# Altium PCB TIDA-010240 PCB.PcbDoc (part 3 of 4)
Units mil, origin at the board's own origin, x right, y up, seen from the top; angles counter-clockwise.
Board outline 5108.27 x 5374.02 mil, 4 copper layers (Top Layer, GND, PWR, Bottom Layer), stack 73.068 mil thick; 370 components, 162 nets, 1073 pads, 556 vias.
Unrouted connection lines stored in the file: 6.
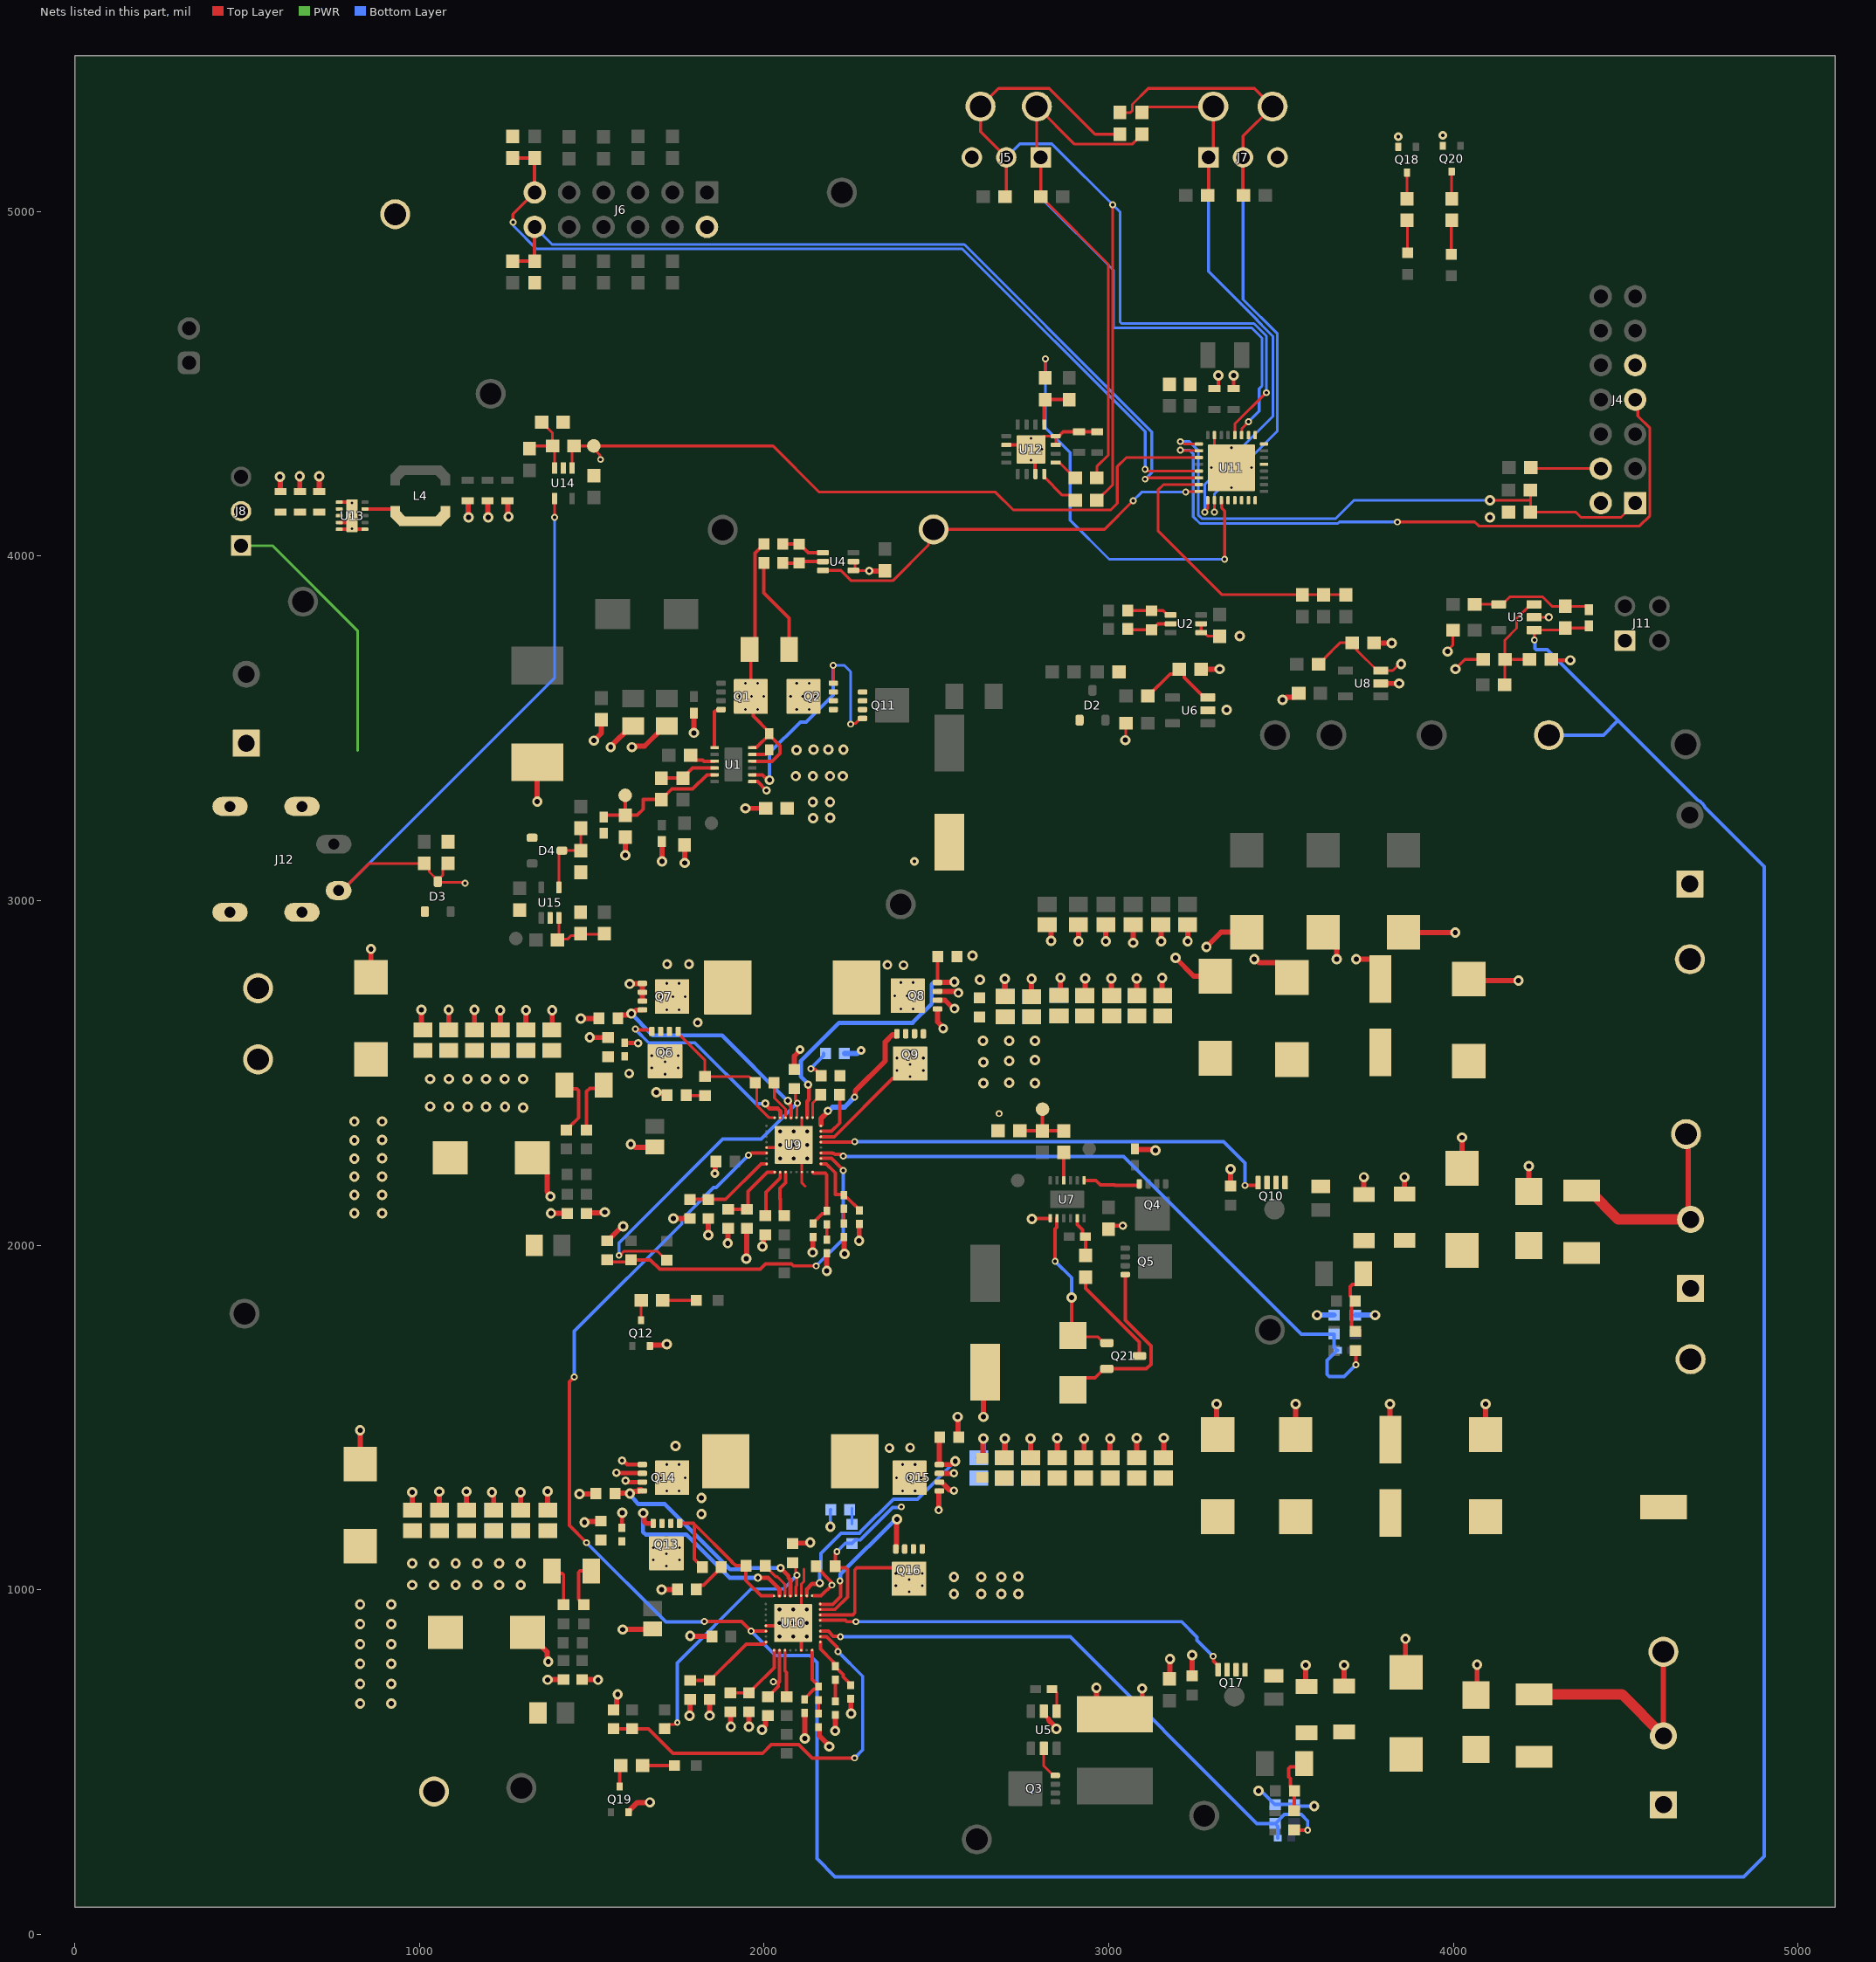
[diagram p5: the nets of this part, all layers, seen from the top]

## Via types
v1: diameter 30, hole 15, Top Layer to Bottom Layer, tented both sides, 281 vias
v2: diameter 19.68, hole 7.87, Top Layer to Bottom Layer, 102 vias
v3: diameter 20, hole 10, Top Layer to Bottom Layer, tented both sides, 99 vias
v4: diameter 24, hole 12, Top Layer to Bottom Layer, tented both sides, 19 vias
v5: diameter 23.62, hole 11.81, Top Layer to Bottom Layer, 18 vias
v6: diameter 19.68, hole 7.87, Top Layer to Bottom Layer, tented both sides, 14 vias
v7: diameter 28, hole 14, Top Layer to Bottom Layer, tented both sides, 13 vias
v8: diameter 25, hole 10, Top Layer to Bottom Layer, tented both sides, 8 vias
v9: diameter 18, hole 8, Top Layer to Bottom Layer, tented both sides, 2 vias

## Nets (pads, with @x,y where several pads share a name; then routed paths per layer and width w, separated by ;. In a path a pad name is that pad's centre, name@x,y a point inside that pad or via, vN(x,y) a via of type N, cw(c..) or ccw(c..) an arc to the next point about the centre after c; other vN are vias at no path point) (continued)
GND: C1.2 C2.2 C3.2 C4.2 C5.2 C6.2 C7.2 C8.2 C9.2 C10.2 C11.2 C12.2 C13.2 C16.2 C17.2 C18.2 C19.2 C21.2 C22.2 C25.2 C26.2 C27.2 C28.2 C29.2 C30.2 C32.2 C33.2 C34.2 C35.2 C36.2 C37.2 C38.2 C39.2 C40.2 C41.2 C42.2 C43.2 C45.2 C46.2 C47.2 C48.2 C49.2 C50.2 C51.2 C52.2 C53.2 C54.2 C57.2 C58.2 C59.2 C62.2 C63.1 C66.2 C67.2 C68.2 C69.2 C70.2 C71.2 C72.2 C73.2 C74.2 C75.1 C76.2 C77.1 C78.2 C79.2 C80.2 C81.2 C82.2 C83.2 C84.2 C85.1 C86.2 C87.2 C88.2 C89.2 C90.2 C91.2 C92.2 C93.2 C94.2 C95.2 C96.2 C97.2 C99.2 C100.2 C101.2 C102.2 C103.2 C104.2 C105.2 C106.2 C107.2 C108.2 C111.2 C112.2 C113.2 C116.2 C117.1 C120.2 C121.2 C122.2 C123.2 C124.2 C125.2 C126.2 C127.2 C128.2 C129.1 C130.2 C131.1 C132.2 C133.2 C134.2 C135.2 C136.2 C137.2 C138.2 C139.2 C140.2 C141.2 C142.2 C143.2 C144.2 C145.2 C146.2 C147.2 C148.2 C149.2 C150.2 C151.2 C152.2 C153.2 C154.2 C155.2 C156.2 C157.2 D1.1 D2.1 D3.1 D4.1 D5.2 D7.2 GND.1 J1.1 J2.1 J3.1 J4.9 J5.3 J6.2 J7.3 J10.1 J11.1 J12.2 Q7.1 Q7.2 Q7.3 Q8.1 Q8.2 Q8.3 Q12.2 Q14.1 Q14.2 Q14.3 Q15.1 Q15.2 Q15.3 Q18.2 Q19.2 Q20.2 R8.1 R9.1 R17.1 R21.1 R27.1 R31.1 R40.1 R42.1 R43.1 R44.2 R51.1 R55.1 R64.1 R66.1 R67.1 R68.2 R85.1 R88.1 R89.1 R91.1 R92.1 R99.1 R100.1 TP12.1 TP13.1 TP14.1 TP15.1 TP17.1 U1.7 U2.1 U2.2 U3.2 U4.1 U4.2 U5.2 U6.2 U7.7 U8.2 U9.5 U9.14 U9.27 U9.33 U10.5 U10.14 U10.27 U10.33 U11.31 U11.33 U12.6 U12.11 U12.15 U12.16 U12.17@2774.5,4310.15 U13.1 U13.4 U13.5 U13.6 U13.11@804.52,4117.36 U14.2 U15.2 | length 11320.9
  Top Layer w8: U9.5@2007.15,2283.52 2038.64,2283.52 v5(2046.52,2291.39) ; v5(2085.89,2291.39) 2109.51,2267.77 U9.14@2109.51,2212.65 2109.51,2181.08 2119.01,2171.58 ; U9.27@2109.51,2370.54 2109.51,2342.51 2121.26,2330.76 v5(2125.26,2330.76) ; 2115.25,1059.71 2115.25,1023.53 2107.71,1016 U10.27@2107.71,982.81 2107.71,954.78 2119.46,943.03 v5(2123.46,943.03) ; U4.1@2259.11,3958.74 2259.82,3958.03 2263.37,3961.58 2263.37,3980.45 2259.49,3984.33 U4.2@2259.11,3984.33 ; U4.1@2259.84,3958.01 2304.28,3958.01 v4(2305,3957.28) ; v2(2774.5,4341.65) 2806,4341.65 2812.89,4348.54 U12.16@2846.35,4348.54 U12.15@2846.35,4322.95 ; v1(3048.55,3465.98) 3049.41,3466.84 3049.41,3514.24 C25.2@3050.28,3515.1 ; U2.2@3267.99,3803.81 U2.1@3267.99,3778.22 3276.85,3778.22 3287.17,3767.9 C13.2@3321.93,3767.9 ; U11.31@3306.82,4351.31 3306.82,4320.74 3312.66,4314.9 v2(3356.03,4314.9) ; v1(3983.57,3723.21) 3983.57,3727.27 3998.85,3742.54 C19.2@3998.85,3785.38 ; v1(4005.88,3672.43) 4033.49,3700.04 R9.1@4086.5,3700.04 ; U3.2@4234.08,3822.78 v4(4277.02,3822.78)
  Top Layer w10: U13.5@767.12,4077.99 802.55,4077.99 v2(804.52,4079.96) 806.49,4077.99 U13.6@841.92,4077.99 ; U13.4@767.12,4097.68 791.34,4097.68 804.52,4110.85 v2(804.52,4117.36) ; U13.1@767.12,4156.73 767.17,4156.68 802.6,4156.68 v2(804.52,4154.77) ; U1.7@1965.61,3345.86 1980.78,3345.86 v4(2006.74,3319.9) ; U10.5@2005.35,895.79 2076.22,895.79 v5(2084.09,903.66) ; U10.14@2107.71,824.92 2107.71,852.54 2119.46,864.29 v5(2123.46,864.29) ; U12.6@2702.65,4322.95 2737.16,4322.95 2743,4317.1 v2(2743,4310.15) ; v2(2774.5,4278.65) 2780.9,4278.65 2785.74,4273.81 2785.74,4252.31 2786.39,4251.66 2786.39,4248.06 2787.3,4247.16 U12.11@2787.3,4238.3 ; v1(2777.18,2076.81) 2778.14,2077.77 2829.93,2077.77 2830.01,2077.85 U7.7@2830.01,2078.74 ; U12.16@2846.35,4348.54 2855.21,4348.54 2867.59,4360.92 C144.2@2966.27,4360.92 ; C146.2@3306.82,4486.06 3312.61,4486.06 3317.61,4491.06 v1(3317.61,4524.63) ; C147.2@3362.13,4486.06 v1(3362.13,4524.63)
  Top Layer w12: v4(1571.29,1339.99) 1572.18,1339.1 1645.8,1339.1 Q14.2@1646.69,1338.21 ; C108.2@1587.04,1179.94 1587.83,1180.73 1587.83,1222.97 v1(1588.63,1223.77) ; v4(1588.07,1375.03) 1591.32,1375.03 1602.56,1363.8 Q14.1@1646.69,1363.8 ; C54.2@1595.53,2587.53 1596.13,2586.94 1633.51,2586.94 v4(1634.1,2586.35) ; v4(1598.1,1316.55) 1601.35,1316.55 1605.28,1312.62 Q14.3@1646.69,1312.62 ; U5.2@2811.56,639.95 2826.15,625.36 2826.15,621.48 ; C28.2@2999.26,2047.24 3011.22,2059.2 3011.22,2057.48 3011.96,2056.74 v4(3040.81,2056.74) ; C18.2@4284.03,3700.04 4286.22,3697.85 v1(4339.14,3697.85)
  Top Layer w15: v1(595.36,4230.34) 596.18,4229.52 596.18,4188.24 C148.2@597,4187.42 ; v1(652.51,4231.69) 652.76,4231.44 652.76,4187.67 C149.2@653.01,4187.42 ; v1(708.81,4231.95) 709.06,4231.7 709.06,4187.67 C150.2@709.31,4187.42 ; C99.2@827.72,1364.92 v1(827.72,1462.99) ; C45.2@859.27,2777.75 v1(859.27,2860) ; C120.2@979.31,1231.06 v1(979.31,1282.89) ; v1(1005.41,2683.17) 1005.41,2629.12 C49.2@1009.89,2624.64 ; v1(1057.53,1285.12) 1057.53,1231.48 C121.2@1057.95,1231.06 ; C50.2@1084.69,2624.64 v1(1084.69,2683.17) ; C122.2@1136.59,1231.06 v1(1136.59,1285.12) ; C151.2@1140.15,4160.67 1141.09,4159.72 1141.09,4113.78 v1(1142.04,4112.83) ; C66.2@1159.5,2624.64 v1(1159.5,2683.17) ; C152.2@1197.63,4160.67 1198.58,4159.72 1198.58,4113.78 v1(1199.53,4112.83) ; v1(1210.25,1282.89) 1210.25,1278.83 1215.22,1273.86 C123.2@1215.22,1231.06 ; C67.2@1234.3,2624.64 v1(1234.3,2682.02) ; C153.2@1255.12,4160.67 1256.72,4159.07 1256.72,4116.33 v1(1258.32,4114.73) ; v1(1293.09,1282.89) 1293.09,1231.83 C103.2@1293.86,1231.06 ; C68.2@1309.1,2624.64 v1(1309.1,2682.02) ; C100.2@1313.55,876.4 1315.51,876.4 1356.24,835.67 1356.24,833.7 1370.72,819.23 1370.72,794.7 v1(1373.59,791.83) ; C46.2@1327.38,2254.25 1329.35,2254.25 1370.08,2213.52 1370.08,2155.75 1380,2145.83 v1(1380,2141.77) ; v1(1341.78,3288.16) D1.1@1341.78,3401.72 ; v1(1371.44,738.88) 1371.85,739.28 1417.67,739.28 C124.2@1418.07,739.68 ; v1(1371.44,1286.12) 1371.44,1232.11 C104.2@1372.5,1231.06 ; v1(1381.39,2092.56) C70.2@1428.41,2092.56 ; C69.2@1383.9,2624.64 1385.1,2625.84 v1(1385.1,2682.02) ; v1(1464.47,1278.17) 1464.96,1278.66 1511.39,1278.66 C116.2@1511.88,1279.15 ; v1(1468.18,2658.46) C62.2@1520.73,2658.46 ; C125.2@1471.98,739.68 1472.38,739.28 1517.74,739.28 v1(1518.14,738.88) ; v1(1478.87,1196.19) 1480.59,1197.91 1524.57,1197.91 C107.2@1526.29,1199.63 ; C71.2@1484.38,2092.56 1486.2,2094.37 1535.88,2094.37 v1(1537.69,2096.19) ; v1(1494.08,2603.28) 1494.46,2602.91 1546.82,2602.91 C53.2@1547.2,2602.53 ; v1(1506,3464.73) 1527.61,3486.34 C9.2@1527.61,3525.13 ; R40.1@1544.8,2013.01 1545.78,2013.01 1587.77,2055 v1(1591,2055) ; v1(1554.88,3445.68) 1554.88,3447.86 1555.08,3447.86 1613.99,3506.78 C10.2@1620.49,3506.78 ; R64.1@1562.79,652.09 1563.78,652.09 1572.03,660.34 1572.03,689.71 1575.04,692.72 v1(1575.04,696.78) ; v1(1589.37,884.72) 1590.3,885.65 1675.58,885.65 C128.2@1676.51,886.58 ; v1(1597,3132.14) R8.1@1597,3185.03 ; Q19.2@1606.54,354.6 1608.29,356.35 1608.29,358.91 1631.24,381.85 1667.49,381.85 v1(1668.74,383.1) ; v1(1610,2758.6) 1610.67,2759.27 1646.15,2759.27 Q7.1@1646.82,2759.94 Q7.2@1646.82,2734.35 Q7.3@1646.82,2708.76 ; v1(1613.07,2292.77) 1617.13,2292.77 1625.96,2283.95 1681.14,2283.95 C74.2@1683.07,2285.88 ; v1(1616.39,3445.68) 1619.26,3448.55 1653.1,3448.55 1711.33,3506.78 C11.2@1717.83,3506.78 ; Q12.2@1668.66,1707.73 1668.66,1708.32 1670.41,1710.07 1715.08,1710.07 v1(1717.43,1712.42) ; v1(1687.6,2443.76) 1690.47,2440.89 1713.23,2440.89 R27.1@1718.61,2435.51 ; v1(1702.12,1001.1) R51.1@1748.39,1001.1 ; C154.2@1703.34,3172.16 1703.57,3171.93 1703.57,3114.01 v1(1703.81,3113.78) ; v1(1736.33,2077.8) R42.1@1784.92,2077.8 ; R88.1@1768.82,3161.67 1769.25,3161.25 1769.25,3110.14 v1(1769.68,3109.72) ; v1(1783.4,634.78) 1784.43,635.8 1784.43,680.99 R66.1@1785.45,682.02 ; v1(1785.45,866.03) 1786.13,865.35 1847.66,865.35 C133.2@1848.33,864.68 ; v1(1796.02,3487.23) 1796.2,3487.41 1796.2,3544.63 C12.2@1796.38,3544.81 ; v1(1837.86,2029.52) C84.2@1837.86,2077.8 ; v1(1841.44,635) 1841.5,635.06 1841.5,681.96 C138.2@1841.56,682.02 ; v8(1857.44,2207.87) 1858.79,2209.22 1858.79,2241.51 C79.2@1860.14,2242.87 ; v1(1894.34,2005.96) 1895.14,2006.75 1895.14,2048.46 R43.1@1895.93,2049.25 ; R67.1@1901.92,645.83 1902.68,645.06 1902.68,603.64 v1(1903.45,602.88) ; v1(1945.82,3268.16) C8.2@2004.14,3268.16 ; v1(1948.59,1961.03) 1949.32,1961.77 1949.32,2048.52 C86.2@1950.06,2049.25 ; v1(1955.9,602.88) 1955.96,602.93 C140.2@1956.01,645.83 C140.2@1956.01,645.83 ; v1(1994,593.69) 1994,596.39 2004.4,606.79 2004.4,629.03 2010.15,634.78 R68.2@2011.13,634.78 ; v1(1994.96,1996.82) 1997.83,1999.69 1997.83,2025.17 R44.2@2003.21,2030.55 ; C130.2@2082.97,1133.88 2084.73,1135.64 2132.18,1135.64 v1(2133.95,1137.41) ; C76.2@2087.79,2510.06 2087.79,2549.22 2103.85,2565.28 v8(2103.85,2567.99) ; C129.1@2117.43,642.65 2117.93,642.15 2117.93,568.97 v1(2118.43,568.47) ; v1(2140.61,1979.36) 2141.45,1980.2 2141.45,2023.2 C75.1@2142.28,2024.03 ; C131.1@2157.78,601.54 2157.78,599.88 2159.97,597.7 2159.97,576.82 2189,547.79 v1(2189,545.08) ; v1(2181.95,1925.61) C77.1@2181.95,1976.78 ; v1(2206.14,590.71) 2206.84,591.41 2206.84,636.81 C132.2@2207,636.97 ; C78.2@2231.4,2023.89 2232.19,2023.1 2232.19,1976.24 v1(2232.99,1975.45) ; C134.2@2251.32,683.99 2251.82,683.49 2251.82,641.18 v1(2252.32,640.68) ; v1(2275.65,2013) 2275.91,2013.26 2275.91,2061.63 C80.2@2276.17,2061.89 ; v4(2305,3957.28) C21.2@2350.64,3957.28 C21.2@2352.12,3955.81 ; Q8.1@2503.17,2685.77 2503.17,2648.56 2519.27,2632.45 v7(2519.27,2628.94) ; Q8.2@2503.17,2711.36 2503.38,2711.14 2524.98,2711.14 2549.02,2687.1 v7(2552.54,2687.1) ; Q8.3@2503.17,2736.95 2555.54,2736.95 2560.23,2732.26 v7(2563.74,2732.26) ; v4(2506.13,1231.48) 2507.36,1232.72 2507.36,1286.65 2507.74,1287.03 Q15.1@2508.6,1287.03 ; Q15.2@2508.6,1312.62 2514.5,1312.62 2537.25,1289.88 2549,1289.88 v4(2550.72,1288.15) ; Q15.3@2508.6,1338.21 v4(2550.72,1338.21) ; v1(2561.71,1501.99) 2563.25,1500.45 2563.25,1444.64 C117.1@2564.78,1443.11 ; C87.2@2633.08,1381.47 2634.74,1383.13 2634.74,1437.21 v1(2636.4,1438.87) ; v1(2636.4,1501.99) 2636.4,1626.72 C29.2@2641.15,1631.47 ; C88.2@2696.38,1383.44 2698.24,1385.29 v1(2698.24,1438.87) ; v1(2698.24,2772.94) 2698.24,2723.6 C42.2@2699.82,2722.02 ; v1(2773.05,1438.87) 2773.05,1383.73 C89.2@2773.34,1383.44 ; C34.2@2776.14,2721.89 v1(2776.14,2772.94) ; U5.2@2811.56,639.95 U5.2@2811.56,647.82 ; C6.2@2821.25,2930.39 2833,2918.64 v1(2833,2883.98) ; 2826.15,621.48 2847.98,599.66 v1(2847.98,596.64) ; C90.2@2850.3,1383.44 v1(2850.3,1439.99) ; C58.2@2855.27,2724.69 2860.05,2729.47 v1(2860.05,2776.64) ; v1(2912.09,2881.99) C5.2@2912.09,2930.39 ; C96.2@2927.26,1383.44 2928.43,1384.6 v1(2928.43,1438.87) ; C57.2@2930.12,2724.6 2931.16,2725.65 v1(2931.16,2774.48) ; v1(2964.04,715.46) 2964.04,684.61 3009.69,638.96 3051.34,638.96 3096.99,684.61 v1(3096.99,713.64) ; v1(2991.57,2881.99) C4.2@2991.57,2930.39 ; C97.2@3004.23,1383.44 v1(3004.23,1438.87) ; v1(3007.88,2774.48) 3007.88,2725.59 C43.2@3008.86,2724.6 ; v1(3070.76,2877.99) 3070.76,2930.09 C3.2@3071.05,2930.39 ; C27.2@3076.02,2279.58 3077.93,2277.68 3133.68,2277.68 v1(3135.58,2275.77) ; C111.2@3081.19,1383.44 3081.45,1383.7 v1(3081.45,1439.99) ; v1(3081.45,2774.48) 3081.45,2724.72 C36.2@3081.57,2724.6 ; C2.2@3150.54,2930.39 3151.64,2929.28 v1(3151.64,2881.99) ; v1(3155.07,2775.99) 3155.07,2725.92 C35.2@3156.39,2724.6 ; C112.2@3158.15,1383.44 3159.78,1385.07 v1(3159.78,1441.07) ; C85.1@3176.07,741.73 3176.95,742.61 3176.95,798.3 v1(3177.83,799.18) ; v1(3193.65,2834.19) 3246.82,2781.02 C40.2@3309.59,2781.02 ; v1(3228.85,2881.99) C1.2@3228.85,2930.39 ; v1(3241.92,810.22) 3242.01,810.14 3242.01,750.39 C113.2@3242.09,750.31 ; C26.2@3267.8,3672.04 3267.99,3672.23 3321.93,3672.23 v1(3322.13,3672.43) ; v1(3283.29,2866) 3325.79,2908.5 C17.2@3399.88,2908.5 ; v1(3313.08,1538.99) 3313.08,1453.56 C94.2@3316.12,1450.52 ; C59.2@3353.6,2171.71 v1(3353.6,2220.57) ; v1(3422.38,2830.14) 3426.44,2830.14 3436.88,2819.7 3490.75,2819.7 3531.48,2778.97 C41.2@3531.48,2777.01 ; v1(3503.94,3582.68) 3508,3582.68 3516,3590.68 3539.98,3590.68 C30.2@3551.18,3601.88 ; C95.2@3542.5,1450.52 v1(3542.5,1538.99) ; v1(3571.35,781.38) 3571.35,721.99 C136.2@3574.32,719.01 ; C155.2@3622.03,2908.5 3661.73,2868.8 v1(3661.73,2830.14) ; C137.2@3682.78,720.98 v1(3682.78,781.38) ; v1(3717.97,2830.14) 3764.41,2830.14 3788.4,2806.15 C48.2@3788.4,2772.69 ; C83.2@3740.47,2147.68 v1(3740.47,2197.62) ; C32.2@3769.33,3748.6 3769.83,3748.09 3820.94,3748.09 v1(3821.44,3747.59) ; U8.2@3789.01,3630.49 v1(3842.99,3630.49) ; v1(3816,1538.99) 3816,1437.01 C102.2@3817.12,1435.89 ; C156.2@3854.93,2908.5 3855.54,2907.89 v1(4005.39,2907.89) ; C82.2@3858.33,2148.66 v1(3858.33,2197.62) ; v1(3861.02,858.01) 3861.02,761.59 C135.2@3862.48,760.13 ; C81.2@4025.07,2223.52 v1(4025.07,2312.83) ; C47.2@4044.76,2772.69 4049,2768.45 v1(4189,2768.45) ; D7.2@4065.78,694.76 4068.68,697.67 v1(4068.68,782.99) ; C101.2@4093.68,1450.52 v1(4093.68,1538.99) ; D5.2@4218.97,2156.28 v1(4218.97,2229.99)
  Bottom Layer w10: v1(2192.15,1183.34) 2192.15,1231.48 R55.1@2193.22,1232.55 ; v1(3434.59,416.19) 3438.42,412.36 3446.42,412.36 3481.61,377.17 C127.2@3482.6,377.17 C126.2@3537.72,377.17 3542.5,372.39 v1(3596.09,372.39)
  Bottom Layer w15: C52.2@1234.3,2624.64 v1(1234.3,2682.02) ; C51.2@1309.1,2624.64 v1(1309.1,2682.02) ; R31.1@2232.99,2556.52 2269.97,2556.52 2279.03,2565.59 v8(2281.74,2565.59) ; C91.2@2622.72,1383.44 2636.4,1397.12 v1(2636.4,1438.87) ; C92.2@2696.38,1383.44 2698.24,1385.29 v1(2698.24,1438.87) ; v1(2698.24,2772.94) 2698.24,2723.6 C38.2@2699.82,2722.02 ; v1(2773.05,1438.87) 2773.05,1383.73 C93.2@2773.34,1383.44 ; C39.2@2776.14,2721.89 v1(2776.14,2772.94) ; C37.2@2855.27,2724.69 2860.05,2729.47 v1(2860.05,2776.64) ; v1@3604.56,1797.27 C73.2@3653.83,1797.27 ; C72.2@3715.87,1797.3 v1(3773.33,1797.25)
  other v1: 3604.54,1797.25 2626.4,2770.41 2604.51,2840.34 3341.68,3553.82 3380.2,3768.37 4106.19,4112.69
  other v2: 3356.03,4198.75 3297.96,4256.82 3356.03,4256.82 3414.1,4256.82 2806,4310.15
  other v3: 2681.87,2382.34
  other v5: 2044.72,864.29 2084.09,864.29 2044.72,903.66 2123.46,903.66 2044.72,943.03 2084.09,943.03 2046.52,2252.02 2085.89,2252.02 2125.26,2252.02 2125.26,2291.39 2046.52,2330.76 2085.89,2330.76
  other v8: 2435.77,3113.78 3839.99,5217.89 3969.41,5221.69
IADPT_A: C84.1 R42.2 U9.8 | length 265
  Top Layer w10: R42.2@1784.92,2132.91 C84.1@1837.86,2132.91 1888.04,2132.91 1991.4,2236.27 U9.8@2007.15,2236.27
IADPT_B: C138.1 R66.2 U10.8 | length 266
  Top Layer w10: R66.2@1785.45,737.14 C138.1@1841.56,737.14 1842.54,737.14 1947.97,842.57 1999.37,842.57 U10.8@2005.35,848.54
IBAT_A: C86.1 R43.2 U9.9 | length 213.6
  Top Layer w10: R43.2@1892.13,2108.17 R43.2@1895.93,2104.37 C86.1@1950.06,2104.37 1953.44,2107.75 1953.44,2156.73 2006.41,2209.7 2008.95,2212.24 U9.9@2030.77,2212.24
IBAT_B: C140.1 R67.2 U10.9 | length 208.5
  Top Layer w10: R67.2@1901.92,700.94 C140.1@1956.01,700.94 1957,700.94 1968.74,712.69 1968.74,713.68 2028.97,773.9 U10.9@2028.97,824.51
ILIM: C23.2 ILIM.1 R13.2 U3.1 U9.6 U10.6 | length 9874.8
  Top Layer w8: v3(4234.89,3756.84) 4234.89,3784.58 U3.1@4234.08,3785.38 R13.2@4316.76,3785.38 ; R13.2@4318.66,3785.57 R13.2@4324.57,3791.47 4387.11,3791.47 C23.2@4393.02,3797.38
  Top Layer w10: v3(1449.08,1617.78) 1434.95,1603.65 1434.95,1186.62 v3(1484.74,1136.83) ; v3(1827,908) 1934.62,908 v3(1962.01,880.61) ; v3(1954.4,2261.33) 1957.11,2261.33 1963.55,2267.77 U9.6@2007.15,2267.77 ; v3@1964.39,877.26 1964.39,877.8 1966.63,880.04 U10.6@2005.35,880.04
  Bottom Layer w10: v3(1449.08,1617.78) 1449.08,1750.52 1761.33,2062.77 1761.33,2075.38 1853.34,2167.4 1860.47,2167.4 v3(1954.4,2261.33) ; v3(1484.74,1136.83) 1714.72,906.85 1825.85,906.85 v3(1827,908) ; v3(1962.01,880.61) 2033.45,809.17 2133.35,809.17 2153.31,789.22 2153.31,219.69 2205.68,167.32 4842.52,167.32 4901.57,226.38 4901.57,3099.31 4730.53,3270.35 ccw(c4686.27,3248.49) 4708.13,3292.75 4477.8,3523.08 ; v3(4234.89,3756.84) 4236.11,3755.62 4236.11,3732.84 4240.36,3728.58 4272.3,3728.58 4477.8,3523.08 ; ILIM.1@4277.02,3480.63 4435.35,3480.63 4477.8,3523.08
IN_ISNS: IN_ISNS.1 U4.6 U11.8 | length 1229.2
  Top Layer w8: U4.6@2170.52,3958.74 2222.93,3958.74 2253.07,3928.6 2373.07,3928.6 2476.68,4032.2 2476.68,4062.63 IN_ISNS.1@2491.8,4077.74 2987.6,4077.74 v3(3070.87,4161.01) v3@3070.87,4161.41 ; v3(3223.5,4185.75) 3224.76,4187.01 3260.62,4187.01 U11.8@3261.54,4187.93
  Bottom Layer w8: v3(3070.87,4161.01) 3095.61,4185.75 v3(3223.5,4185.75)
IN_ISNS_N: C8.1 C45.1 C46.1 C49.1 C50.1 C51.1 C52.1 C66.1 C67.1 C68.1 C69.1 C99.1 C100.1 C103.1 C104.1 C105.1 C106.1 C120.1 C121.1 C122.1 C123.1 J8.1 Q2.5 Q2.6 Q2.7 Q2.8 Q2.9 R1.1 R10.2 R24.1 R26.2 R32.2 R48.1 R50.2 R56.2 Vin_PROT.1 | length 1388.3
  Top Layer w10: R48.1@1384.63,1054.66 1391.35,1047.94 1413.39,1047.94 1418.07,1043.25 R50.2@1418.07,956.52 ; R24.1@1420.53,2464.89 1431.21,2454.21 1457.2,2454.21 1461.88,2449.53 1461.88,2369.85 1439.17,2347.13 1439.17,2346.15 1427.42,2334.4 R26.2@1426.44,2334.4 ; R10.2@1999.08,3980.45 1999.08,3893.3 2072.1,3820.28 R1.1@2072.1,3729.55 ; v2(2112.44,3593.14) Q2.9@2123.73,3581.86
  PWR w8: J8.1@482.28,4030.59 573.63,4030.59 820.41,3783.81 820.41,3435.93
  other v1: 827.72,669.57 918.27,669.57 827.72,727.23 918.27,727.23 827.72,784.88 918.27,785.57 827.72,842.54 918.27,842.54 827.72,900.2 918.27,900.2 827.72,957.85 918.27,957.85 979.31,1013.9 1042.22,1013.9 1105.13,1013.9 1168.04,1013.9 1230.95,1013.9 1293.86,1013.9 979.31,1076.45 1042.22,1076.45 1105.13,1076.45 1168.04,1076.45 1230.95,1076.45 1293.86,1076.45 811.07,2092.56 891.26,2092.56 811.07,2145.94 891.26,2145.94 811.07,2199.31 891.26,2199.31 811.07,2251.71 891.26,2252.69 811.07,2304.87 891.26,2306.06 811.07,2359.44 891.26,2359.44 1301.09,2399.83 1085.2,2402.36 1139.81,2402.36 1193.14,2402.36 1248.29,2401.74 1031.23,2402.92 1031.23,2482.64 1085.2,2482.64 1139.17,2482.64 1193.14,2482.64 1247.12,2482.64 1301.09,2482.64 2142.51,3239.77 2191.75,3240.9 2141.35,3286.74 2191.05,3286.74 2091.98,3361.78 2141.51,3361.78 2191.05,3361.78 2228.17,3361.78 2094.43,3437.47 2143.26,3438.18 2186.41,3438.36 2230.14,3438.87
  other v2: 2094.63,3554.76 2130.26,3554.76 2148.07,3593.14 2094.63,3631.53 2130.26,3631.53
  other v6: 2076.81,3593.14
IN_ISNS_P: C15.1 Q1.5 Q1.6 Q1.7 Q1.8 Q1.9 R1.2 R11.1 U1.10 U1.12 | length 815.1
  Top Layer w10: U1.10@1965.61,3404.91 2023.42,3404.91 2045.73,3427.22 2045.73,3450.42 C15.1@2014.83,3481.33 ; U1.12@1965.61,3444.28 1965.69,3444.36 1977.86,3444.36 C15.1@2014.83,3481.33 ; R11.1@1999.08,4035.04 1999.08,4034.05 1973.33,4008.31 1973.33,3744.95 R1.2@1957.93,3729.55 1961.57,3725.91 1961.57,3595.21 v2(1963.64,3593.14) 1968.42,3588.36 1968.42,3535.61 2014.83,3489.2 C15.1@2014.83,3485.26 C15.1@2014.83,3481.33
  other v2: 1945.82,3554.76 1981.45,3554.76 1928.01,3593.14 1945.82,3631.53 1981.45,3631.53
  other v6: 1999.27,3593.14
IN_VSNS: D4.3 R96.1 R99.2 U15.4 | length 231.3
  Top Layer w8: U15.4@1404.64,3038.77 1404.64,3138.77 1411.38,3145.51 D4.3@1413.39,3145.51 R99.2@1468.18,3145.51 R96.1@1468.18,3210.49
MSP_I2C_Master_RST: R69.1 U11.11 | length 1227
  Top Layer w8: R69.1@2815.84,4517.56 2815.84,4567.26 2816.32,4567.75 2817.87,4567.75 2815.84,4569.78 v3(2815.84,4572.81) ; U11.11@3326.5,4162.34 3327.43,4161.41 3327.43,4140.13 3336.49,4131.07 3336.49,3991.26 v3(3336.29,3991.07)
  Bottom Layer w8: v3(2815.84,4572.81) 2815.84,4372.95 2887.86,4300.94 2887.86,4104.33 3001.12,3991.07 v3(3336.29,3991.07)
MSP_P2.3: U11.14
MSP_P2.7: U11.25
MSP_P3.0: U11.12
MSP_P3.1: U11.16
MSP_P3.3: U11.13
MSP_P3.4: U11.15
MSP_P3.5: U11.26
MSP_P3.7: U11.21
MSP_P4.2: U11.24
MSP_SYS_CURR: R104.2 R105.2 R106.2 U11.7 | length 865.3
  Top Layer w8: U11.7@3261.54,4207.61 3158.54,4207.61 3142.8,4191.86 3142.8,4074.09 3328.91,3887.98 R106.2@3561.65,3887.98 R104.2@3623.39,3887.98 R105.2@3687.98,3887.98
MSP_Tool: J4.2
MSP_UCB0_SCL: J7.2 R74.1 R108.2 TP4.1 U11.10 | length 1979.9
  Top Layer w8: R108.2@3032.48,5287.4 3063.18,5287.4 3068.55,5292.77 3068.55,5311.49 3114.68,5357.62 3422.89,5357.62 TP4.1@3475.39,5305.12 3389.63,5219.35 J7.2@3389.63,5157.48 3389.63,5049.06 R74.1@3391.4,5047.29 ; v3(3306.82,4127.82) U11.10@3306.82,4162.34
  Bottom Layer w8: v3(3306.82,4127.82) 3306.82,4180.96 3489.34,4363.49 3489.34,4645.35 3389.63,4745.06 J7.2@3389.63,5157.48
MSP_UCB0_SDA: J7.1 R73.1 R107.2 TP2.1 U11.9 | length 1706.8
  Top Layer w8: R107.2@3096.25,5288.08 3096.25,5289.06 3110.95,5303.76 3302.09,5303.76 TP2.1@3303.45,5305.12 3303.45,5171.3 J7.1@3289.63,5157.48 3289.63,5050.43 R73.1@3286.5,5047.29 ; v3(3278.35,4127.82) 3278.35,4129.74 3287.13,4138.52 U11.9@3287.13,4162.34
  Bottom Layer w8: v3(3278.35,4127.82) 3278.35,4207.67 3476.34,4405.66 3476.34,4638.23 3458.41,4656.17 3430.18,4684.39 3430.18,4686.12 3289.63,4826.67 J7.1@3289.63,5157.48
MSP_UCB1_SCL: J5.2 R65.1 R93.1 R108.1 TP3.1 U11.28 | length 3167.8
  Top Layer w8: R65.1@2698.82,5043.46 2702.65,5047.29 J5.2@2702.65,5157.48 2627.95,5232.18 TP3.1@2627.95,5305.12 2680.45,5357.62 2827.07,5357.62 2960.28,5224.41 R108.1@3032.48,5224.41 ; R93.1@2965.55,4162.34 2966.54,4162.34 3011.81,4207.61 v3(3011.81,5019.69) ; U11.28@3365.87,4351.31 3365.87,4383.85 3456.41,4474.39 v3(3457.34,4474.39)
  Bottom Layer w8: J5.2@2702.65,5157.48 2742.02,5196.85 2835.06,5196.85 3032.78,4999.13 3032.78,4679.88 3037.47,4675.2 3420.99,4675.2 3457.34,4638.85 v3(3457.34,4474.39)
MSP_UCB1_SDA: J5.1 R45.1 R94.1 R107.1 TP1.1 U11.27 | length 2870.9
  Top Layer w8: R94.1@2965.55,4227.3 2965.55,4259.97 2998.81,4293.23 2998.81,4847.69 2818.73,5027.77 2818.73,5028.76 2804.03,5043.46 R45.1@2803.04,5043.46 2803.04,5157.09 J5.1@2802.65,5157.48 2791.32,5168.81 TP1.1@2791.32,5305.12 2900.72,5195.72 3067.88,5195.72 3096.25,5224.1 R107.1@3096.25,5225.08 ; U11.27@3385.56,4351.31 3386.48,4352.23 3386.48,4371 v3(3405.24,4389.76)
  Bottom Layer w8: J5.1@2802.65,5157.48 2802.65,5040.9 3013.78,4829.77 3013.78,4665.35 3016.94,4662.2 3415.61,4662.2 3444.34,4633.46 3444.34,4493.81 3436.59,4486.06 3436.59,4421.11 v3(3405.24,4389.76)
NetBAT_A_1: BAT_A.1 J2.2 R36.2 | length 603.6
  Top Layer w15: BAT_A.1@4675.2,2322.83 4681.69,2316.34 4681.69,2081.37 J2.2@4683.62,2079.43
  Top Layer w20: J2.2@4683.62,2079.43 J2.2@4688.18,2074.88
  Top Layer w30: R36.2@4372.75,2158.93 4394.4,2158.93 4478.45,2074.88 J2.2@4688.18,2074.88
NetBAT_B_1: BAT_B.1 J3.2 R60.2 | length 669.6
  Top Layer w15: J3.2@4609.54,576.1 BAT_B.1@4609.54,820.17
  Top Layer w30: R60.2@4233.92,696.65 4488.99,696.65 J3.2@4609.54,576.1
NetC14_1: C14.1 R4.1 U2.4 | length 130
  Top Layer w10: R4.1@3054.7,3842.19 3157.76,3842.19 3170.55,3829.4 U2.4@3179.41,3829.4
NetC14_2: C14.2 R3.1 U2.5 | length 133
  Top Layer w10: R3.1@3054.7,3789.04 3057.37,3786.37 C14.2@3124.38,3786.37 3125.36,3786.37 3142.8,3803.81 U2.5@3179.41,3803.81
NetC15_2: C15.2 U1.11 | length 57.1
  Top Layer w10: U1.11@1965.61,3424.6 2005.34,3424.6 2014.83,3434.08 C15.2@2014.83,3438.02
NetC18_1: C18.1 R7.2 R9.2 U3.3 | length 356.5
  Top Layer w8: R7.2@4148.03,3626.45 4149.5,3627.92 R9.2@4149.5,3700.04 ; C18.1@4221.04,3700.04 R9.2@4149.5,3700.04 ; U3.3@4243.92,3860.19 U3.3@4234.08,3860.19 4224.24,3860.19 4183.46,3819.41 4183.46,3790.7 4149.5,3756.73 R9.2@4149.5,3700.04
NetC20_1: C20.1 R11.2 U4.4 | length 126.7
  Top Layer w10: R11.2@2054.2,4035.04 C20.1@2101.63,4035.04 2102.61,4035.04 2127.73,4009.92 U4.4@2170.52,4009.92
NetC20_2: C20.2 R10.1 U4.5 | length 118.4
  Top Layer w10: R10.1@2054.2,3980.45 2054.73,3979.92 C20.2@2101.63,3979.92 2106.04,3984.33 U4.5@2170.52,3984.33
NetC23_1: C23.1 R12.2 R13.1 U3.4 | length 355.6
  Top Layer w8: R12.2@4061.84,3860.19 U3.4@4131.72,3860.19 4141.56,3860.19 4163.37,3882 4258.7,3882 4286.42,3854.28 R13.1@4322.66,3854.28 ; R13.1@4324.57,3854.47 4386.21,3854.47 4393.02,3847.66 C23.1@4393.02,3844.62
NetC24_2: C24.2 U5.1 | length 72
  Top Layer w8: C24.2@2835.18,711.8 2839.12,711.8 2848.96,701.96 U5.1@2848.96,647.82
NetC26_1: C26.1 R14.2 U6.3 | length 246.4
  Top Layer w10: R14.2@3113.27,3594.55 3114.25,3594.55 3178.03,3658.34 3191.1,3658.34 C26.1@3204.8,3672.04 3205.79,3672.04 3219.49,3658.34 3219.49,3648.05 3277.64,3589.9 U6.3@3287.48,3589.9
NetC31_2: C31.2 R84.1 U7.11 | length 114.4
  Top Layer w10: U7.11@2908.83,2071.53 2908.83,2059.56 2923.54,2044.84 2923.54,2031.98 2930.36,2025.17 C31.2@2932.65,2025.17 2933.07,2024.75 R84.1@2933.07,1970.47 R84.1@2933.07,1968.5
NetC32_1: C32.1 R19.2 U8.3 | length 312.4
  Top Layer w8: R19.2@3608.9,3686.59 3609.88,3686.59 3645.99,3722.7 3645.99,3723.69 3670.9,3748.6 C32.1@3706.34,3748.6 3707.32,3748.6 3718.52,3737.4 3718.52,3728.54 3779.17,3667.89 3823.97,3667.89 3843.42,3687.34 v1(3848.37,3687.34)
NetC33_1: C33.1 C34.1 C35.1 C36.1 C37.1 C38.1 C39.1 C40.1 C41.1 C42.1 C43.1 C47.1 C48.1 C57.1 C58.1 Q9.5 Q9.6 Q9.7 Q9.8 Q9.9 Q10.1 Q10.2 Q10.3 R25.1 U9.22 | length 350.2
  Top Layer w10: U9.22@2164.63,2315.01 2203.62,2315.01 2372.76,2484.16 2381.46,2484.16 2385.33,2488.03 Q9.5@2385.33,2491.9 ; Q9.5@2385.33,2489.93 2422.93,2527.53 Q9.9@2423.72,2527.53
  other v1: 2636.4,2470.58 2785.58,2470.58 2710.82,2472.16 2636.4,2531.52 2710.82,2535.05 2785.9,2537.37 2634.9,2593.06 2710.82,2593.6 2785.58,2593.6
  other v2: 2385.33,2507.65 2462.11,2507.65 2423.72,2525.46 2385.33,2543.28 2462.11,2543.28 2423.72,2561.09
  other v6: 2423.72,2489.83
NetC44_2: C44.2 C81.1 C82.1 C83.1 D5.1 R23.2 R29.2 R36.1 | length 205.6
  Top Layer w10: R29.2@3715.87,1750.05 3714.88,1750.05 3704.13,1760.8 3704.13,1766.45 3703.93,1766.66 3703.93,1826.01 3715.38,1837.47 3715.38,1839.43 3700.98,1853.83 3700.98,1880.1 3706.84,1885.96 3717.91,1885.96 3738.5,1906.55 R23.2@3738.5,1917.38
NetC53_1: C53.1 C54.1 Q6.5 Q6.6 Q6.7 Q6.8 Q6.9 R24.2 R30.2 | length 169.8
  Top Layer w10: R30.2@1484.38,2334.4 1484.38,2446.09 1494.08,2455.79 1525.61,2455.79 R24.2@1534.71,2464.89
  other v2: 1674.09,2514.4 1750.86,2514.4 1712.47,2532.22 1674.09,2550.03 1750.86,2550.03 1712.47,2567.85
  other v6: 1712.47,2496.59
  other v7: 1608.28,2498.66
NetC55_1: C55.1 C60.2 L2.1 Q6.1 Q6.2 Q6.3 Q7.5 Q7.6 Q7.7 Q7.8 Q7.9 U9.32 | length 451.1
  Top Layer w8: Q6.1@1750.86,2620.7 1750.86,2614.8 1828.29,2537.37 C55.1@1828.29,2489.65 1956.15,2489.65 1961.13,2484.67 1962.12,2484.67 1973.86,2472.92 C60.2@1973.86,2471.93 1978.36,2467.43 1978.36,2406.95 2015.18,2370.13 U9.32@2030.77,2370.13
  other v2: 1717.49,2683.17 1753.12,2683.17 1699.68,2721.55 1735.31,2721.55 1717.49,2759.94 1753.12,2759.94
  other v6: 1770.94,2721.55
  other v7: 1807.18,2646.24 1718.74,2815.83 1782.18,2815.83
NetC55_2: C55.2 R27.2 | length 55
  Top Layer w8: R27.2@1773.73,2435.51 1774.71,2434.53 C55.2@1828.29,2434.53
NetC56_1: C56.1 U9.25 | length 77
  Top Layer w8: U9.25@2141.01,2370.54 2141.01,2412.76 2164.19,2435.94 C56.1@2164.19,2436.92 C56.1@2164.19,2437.91
NetC56_2: C56.2 C61.1 L2.2 Q8.5 Q8.6 Q8.7 Q8.8 Q8.9 Q9.1 Q9.2 Q9.3 U9.23 | length 151.3
  Top Layer w10: U9.23@2164.63,2330.76 2195.46,2330.76 2219.3,2354.6 C56.2@2219.3,2436.92 C56.2@2219.3,2441.35
  other v2: 2396.87,2685.77 2432.5,2685.77 2414.68,2724.15 2450.31,2724.15 2396.87,2762.54 2432.5,2762.54
  other v6: 2379.05,2724.15
  other v7: 2404.43,2813.12 2358.1,2813.81
NetC60_1: C60.1 U9.30 | length 115.6
  Top Layer w8: C60.1@2028.98,2471.93 2029.99,2470.93 2029.99,2427.37 2062.28,2395.07 U9.30@2062.27,2370.13
NetC61_2: C61.2 R31.2 | length 97.1
  Top Layer w10: v3(2135.97,2512.52) 2137.5,2510.99 2147.07,2510.99 2165.17,2492.89 C61.2@2165.17,2491.9
  Bottom Layer w10: v3(2135.97,2512.52) 2135.97,2513.64 2172.34,2550.01 R31.2@2172.34,2556.27
NetC62_1: C62.1 Q7.4 U9.29 | length 694.7
  Top Layer w12: v4(2068.82,2419.65) 2068.82,2416.41 2075.7,2409.52 2075.7,2405.49 2078.01,2403.18 U9.29@2078.01,2370.13
  Top Layer w15: C62.1@1575.85,2658.46 1575.85,2659.44 1584.1,2667.69 1605.78,2667.69 1610.53,2672.44 1618.64,2672.44 1629,2682.79 1646.45,2682.79 Q7.4@1646.82,2683.17
  Bottom Layer w12: v1(1614.59,2672.44) 1642.13,2644.9 1642.13,2643.71 1676.42,2609.42 1877.64,2609.42 2067.4,2419.65 v4(2068.82,2419.65)
NetC63_2: C63.2 Q8.4 U9.26 | length 875.1
  Top Layer w8: Q8.4@2503.17,2762.54 Q8.4@2503.54,2762.92 ; C63.2@2503.17,2836.85 C63.2@2504.15,2837.84
  Top Layer w10: Q8.4@2503.17,2762.54 C63.2@2503.17,2836.85
  Top Layer w12: U9.26@2125.26,2370.54 2125.26,2418.22 2129.78,2422.75 2129.78,2463.58 v4(2127.49,2465.88)
  Top Layer w15: Q8.4@2503.54,2762.91 2550.62,2762.91 v1(2552.15,2764.45)
  Bottom Layer w12: v4(2127.49,2465.88) 2127.49,2469.13 2106.5,2490.12 2106.5,2534.58 2217.48,2645.57 2430.76,2645.57 2485.95,2700.76 2485.95,2757.42 2492.98,2764.45 v1(2552.15,2764.45)
NetC75_2: C75.2 R34.2 U9.16 | length 206.4
  Top Layer w10: U9.16@2141.01,2212.65 2143.96,2209.7 2177.26,2209.7 2181.95,2205.01 R34.2@2181.95,2099.81 2181.95,2097.85 2176.1,2092 2168.91,2092 2142.28,2065.37 C75.2@2142.28,2063.4
NetC77_2: C77.2 R34.1 | length 44.3
  Top Layer w8: C77.2@2181.95,2016.15 R34.1@2181.95,2060.44
NetC78_1: C78.1 R33.2 | length 43.1
  Top Layer w8: C78.1@2231.4,2063.26 R33.2@2231.4,2106.33
NetC80_1: C80.1 R33.1 U9.17 | length 206.4
  Top Layer w10: U9.17@2165.04,2236.27 2180.38,2236.27 2206.51,2210.14 2206.51,2146.85 2230.26,2146.85 R33.1@2231.4,2145.7 2231.4,2143.73 2237.24,2137.89 2241.5,2137.89 2276.17,2103.22 C80.1@2276.17,2101.26
NetC87_1: C87.1 C88.1 C89.1 C90.1 C91.1 C92.1 C93.1 C94.1 C95.1 C96.1 C97.1 C101.1 C102.1 C111.1 C112.1 Q16.5 Q16.6 Q16.7 Q16.8 Q16.9 Q17.1 Q17.2 Q17.3 R49.1 U10.22 | length 386
  Top Layer w8: Q16.5@2382.08,994.46 2407.77,994.46 v6(2420.57,994.46)
  Top Layer w10: U10.22@2162.83,927.28 2257.27,927.28 2263.13,933.14 2263.13,1058.24 2268.99,1064.1 2375.1,1064.1 Q16.9@2378.87,1067.88
  other v1: 2550.72,988.31 2630.12,988.31 2688.25,988.31 2738.08,988.31 2550.72,1037.14 2630.12,1037.14 2688.25,1037.14 2737.32,1038.4
  other v2: 2382.18,1012.28 2458.95,1012.28 2420.57,1030.09 2382.18,1047.91 2458.95,1047.91 2420.57,1065.72
NetC98_2: C98.2 C135.1 C136.1 C137.1 D7.1 R47.2 R53.2 R60.1 | length 181.2
  Top Layer w10: R53.2@3537.72,358.47 3538.89,359.64 C98.2@3538.89,416.19 3527.14,427.94 3527.14,452.7 3522.32,457.53 3522.32,481.31 3527,485.99 3557.35,485.99 R47.2@3567.24,495.89
NetC107_1: C107.1 C108.1 Q13.5 Q13.6 Q13.7 Q13.8 Q13.9 R48.2 R54.2 | length 139.9
  Top Layer w10: R54.2@1477.13,956.52 1476.14,956.52 1464.39,968.27 1464.39,969.26 1461.4,972.25 1461.4,1049.98 1466.09,1054.66 R48.2@1498.8,1054.66
  other v2: 1678.09,1086.44 1754.86,1086.44 1716.47,1104.25 1678.09,1122.07 1754.86,1122.07 1716.47,1139.88
  other v6: 1716.47,1068.62
NetC109_1: C109.1 C114.2 L3.1 Q13.1 Q13.2 Q13.3 Q14.5 Q14.6 Q14.7 Q14.8 Q14.9 U10.32 | length 518.2
  Top Layer w10: Q13.1@1754.86,1192.74 1795,1192.74 1797.6,1190.14 ; C109.1@1820.77,1065.76 1820.77,1066.74 1797.6,1089.91 1797.6,1190.14 ; 2025.03,982.4 1991.39,982.4 1947.19,1026.6 1947.19,1068.98 C114.2@1948.09,1069.88 1917.86,1069.88 1906.82,1080.92 1906.82,1081.45 1798.13,1190.14 1797.6,1190.14
  other v1: 1818.24,1220.15 1818.24,1266.96 1743.03,1417.67
  other v2: 1717.36,1287.03 1752.99,1287.03 1699.54,1325.41 1735.17,1325.41 1717.36,1363.8 1752.99,1363.8
  other v6: 1770.8,1325.41
NetC109_2: C109.2 R51.2 | length 100.3
  Top Layer w10: R51.2@1803.5,1001.1 1803.5,1002.09 1814.25,1012.83 1823.95,1012.83 1875.89,1064.77 C109.2@1875.89,1065.76
NetC110_1: C110.1 U10.25 | length 139.9
  Top Layer w10: 2143.14,982.81 2165.47,982.81 v3(2196.56,1013.9) 2194.65,1015.81 2194.65,1024.01 2151.02,1067.64 C110.1@2151.02,1068.62
NetC110_2: C110.2 C115.1 L3.2 Q15.5 Q15.6 Q15.7 Q15.8 Q15.9 Q16.1 Q16.2 Q16.3 U10.23 | length 498
  Top Layer w10: U10.23@2162.83,943.03 2205.64,943.03 2242.09,979.47 2242.09,1058.52 2236.23,1064.38 2210.38,1064.38 C110.2@2206.14,1068.62 2207,1069.48 2207,1105.05 2211.21,1109.26 v3(2211.21,1110.56)
  Bottom Layer w10: v3(2211.21,1110.56) 2235.31,1134.66 C115.1@2255.19,1134.66 2265.2,1144.67 2278.86,1144.67 2373.1,1238.91 2395.81,1238.91 v3(2397.72,1240.82)
  other v2: 2402.3,1287.03 2437.93,1287.03 2420.11,1325.41 2455.74,1325.41 2402.3,1363.8 2437.93,1363.8
  other v6: 2384.48,1325.41
  other v7: 2363.59,1411.56 2423.77,1412.7
NetC114_1: C114.1 U10.30 | length 113.6
  Top Layer w8: C114.1@2003.21,1069.88 2003.21,1068.9 2034.18,1037.93 2038.3,1037.93 2060.47,1015.76 U10.30@2060.47,982.4
NetC115_2: C115.2 R55.2 | length 46.1
  Bottom Layer w8: C115.2@2254.89,1191.16 R55.2@2254.89,1237.22
NetC116_1: C116.1 Q14.4 U10.29 | length 698.6
  Top Layer w12: v4(2047.5,1063.22) 2070.25,1040.48 2070.25,1035.05 2076.22,1029.08 U10.29@2076.22,982.4
  Top Layer w15: C116.1@1580.15,1281.12 1609,1281.12 v1(1610.56,1279.56) 1615.97,1279.56 1622.53,1286.12 1636.63,1286.12 Q14.4@1637.53,1287.03 ; Q14.4@1636.63,1290.85 1642.87,1290.85 Q14.4@1646.69,1287.03
  Bottom Layer w12: v1(1610.56,1279.56) 1610.56,1274.69 1626.56,1258.69 1626.56,1257.38 1635.05,1248.89 1712.07,1248.89 1901.25,1059.71 1936.81,1059.71 1940.32,1063.22 v4(2047.5,1063.22)
NetC117_2: C117.2 Q15.4 U10.26 | length 782
  Top Layer w12: U10.26@2123.46,982.81 2123.46,1001.89 2138.81,1017.24 2158.93,1017.24 v4(2161.22,1019.54)
  Top Layer w15: C117.2@2509.66,1443.11 2508.6,1442.05 2508.6,1367.49 Q15.4@2508.6,1363.8 2542.45,1363.8 2551.84,1373.18 v1(2554.55,1373.18)
  Bottom Layer w10: v4(2161.22,1019.54) 2161.22,1047.44 2165.32,1051.54 2165.32,1106.24 2223.11,1164.03 2276.06,1164.03 2281.92,1169.88 2281.92,1170.01 2375.09,1263.18 2444.55,1263.18 v1(2554.55,1373.18)
NetC129_2: C129.2 R58.2 U10.16 | length 171.4
  Top Layer w10: C129.2@2117.43,682.02 2117.43,683.99 2144.89,711.45 2151.94,711.45 2157.78,717.29 R58.2@2157.78,719.26 2157.78,721.23 2139.21,739.81 U10.16@2139.21,824.92
NetC131_2: C131.2 R58.1 | length 39
  Top Layer w10: C131.2@2157.78,640.91 R58.1@2157.78,679.89
NetC132_1: C132.1 R57.2 | length 62.5
  Top Layer w10: C132.1@2207,676.34 R57.2@2207,738.88
NetC134_1: C134.1 R57.1 U10.17 | length 161.7
  Top Layer w10: U10.17@2163.24,848.54 2163.24,828.45 2201.15,790.53 2201.15,782.12 2229.16,754.12 2229.16,747.49 2251.32,725.33 C134.1@2251.32,723.36
NetC139_1: C139.1 R6.1 R8.2 TP5.1 U1.5 | length 446.5
  Top Layer w10: C139.1@1534.71,3243.03 1539.7,3248.02 R8.2@1597,3248.02 ; TP5.1@1597,3305.74 R8.2@1597,3248.02 ; U1.5@1856.16,3365.54 1856.09,3365.46 1833.82,3365.46 1792.8,3324.44 1732.28,3324.44 1701.76,3293.93 1649.04,3293.93 1649.04,3265.64 1631.42,3248.02 R8.2@1597,3248.02
NetC148_1: C148.1 C149.1 C150.1 J8.2 U13.2 U13.3
NetD6_1: D6.1 R46.2 | length 97.4
  Top Layer w8: R46.2@1706.06,1840.2 D6.1@1803.51,1840.2
NetD8_1: D8.1 R70.2 | length 93.4
  Top Layer w10: R70.2@1646.89,490.1 D8.1@1740.27,490.1
NetD9_1: D9.1 R86.2 | length 106.9
  Top Layer w8: D9.1@3988.02,4870.79 D9.1@3993.93,4876.69 ; D9.1@3993.93,4876.5 D9.1@3993.93,4876.69 ; R86.2@3995,4974.56 3993.93,4973.5 D9.1@3993.93,4876.69
NetD10_1: D10.1 Q21.1 U7.8 | length 471.6
  Top Layer w8: D10.1@2892.44,1741.82 2899.54,1734.72 2968.14,1734.72 2986.7,1716.15 Q21.1@2994.58,1716.15
  Top Layer w10: v3(2844.66,1953.81) 2844.66,2047.34 2849.62,2052.3 2849.62,2078.66 U7.8@2849.7,2078.74 ; D10.1@2892.44,1741.82 v1(2892.44,1848.42)
  Bottom Layer w10: v3(2844.66,1953.81) 2892.44,1906.03 v1(2892.44,1848.42)
NetD10_2: D10.2 Q5.4 Q21.2 | length 548
  Top Layer w10: D10.2@2896.45,1580.33 2930.82,1614.7 2960.05,1614.7 2986.7,1641.35 Q21.2@2994.58,1641.35 3109.01,1641.35 3122.58,1654.92 3122.58,1707.19 3047.79,1781.99 Q5.4@3047.79,1914.9
NetD11_1: D11.1 R90.2 | length 94.8
  Top Layer w8: D11.1@3866.57,4881.58 R90.2@3866.57,4973.58
  Top Layer w20: R90.2@3865.58,4974.56 R90.2@3866.57,4973.58 ; D11.1@3866.57,4881.58 D11.1@3867.55,4880.59
NetJ4_4: J4.4 R71.2 | length 204.3
  Top Layer w8: R71.2@4224.41,4256.82 4227.06,4254.17 J4.4@4427.66,4254.17
NetL4_1: L4.1 U13.9 | length 90.7
  Top Layer w10: U13.9@841.92,4137.05 921.93,4137.05 L4.1@929.52,4129.47
NetQ1_4: Q1.4 U1.1 | length 126
  Top Layer w10: U1.1@1856.16,3444.28 1856.16,3548.8 1859.25,3551.88 1872.28,3551.88 Q1.4@1875.15,3554.76
NetQ2_1: Q2.1 Q2.2 Q2.3 Q11.1 Q11.2 Q11.3
NetQ2_4: Q2.4 Q11.4 U1.8 | length 779.4
  Top Layer w8: Q2.4@2200.93,3631.53 v3(2200.93,3683.29) ; v3(2251.02,3512.59) 2253.32,3514.89 2265.6,3514.89 2279.78,3529.06 Q11.4@2285.68,3529.06
  Top Layer w10: U1.8@1965.61,3365.54 1995.03,3365.54 2010.33,3350.24 v7(2015.75,3350.24)
  Bottom Layer w8: v3(2200.93,3683.29) 2232.07,3683.29 2251.02,3664.33 v3(2251.02,3512.59)
  Bottom Layer w10: v7(2015.75,3350.24) 2015.75,3429.62 2104.91,3518.79 2122.35,3518.79 2200.93,3597.36 v3(2200.93,3683.29)
NetQ3_4: Q3.4 U5.5 | length 95.5
  Top Layer w8: U5.5@2811.56,539.55 2811.56,488.81 2839.06,461.31 Q3.4@2844.97,461.31
NetQ4_4: Q4.4 U7.1 | length 167.3
  Top Layer w10: U7.1@2928.44,2188.18 2962.59,2188.18 2975.59,2175.18 3017.03,2175.18 3018.03,2174.18 3084.46,2174.18 Q4.4@3088.34,2178.1
NetQ6_4: Q6.4 U9.31 | length 593.3
  Top Layer w10: v3(1626,2627.15) 1627.91,2625.23 1670.21,2625.23 1674.09,2621.36 Q6.4@1674.09,2620.7
  Top Layer w12: v4(2003.29,2411.72) 2003.29,2408.48 2014.6,2397.17 2014.6,2396.88 2039.26,2396.88 2047.28,2388.86 2047.28,2370.9 U9.31@2046.52,2370.13
  Bottom Layer w10: v3(1626,2627.15) 1626,2626.82 1665.12,2587.69 1799.12,2587.69 1976.17,2410.64 2002.2,2410.64 v4(2003.29,2411.72)
NetQ9_4: Q9.4 U9.24 | length 392
  Top Layer w15: 2164.63,2350.45 2164.63,2367.15 2185.17,2387.68 v4(2185.17,2390.12) ; v3(2262.52,2430.2) 2264.44,2432.11 2264.44,2447.96 2351.52,2535.05 2351.52,2590.2 2372.8,2611.47 2382.86,2611.47 Q9.4@2385.33,2613.94 2385.33,2610.04 Q9.4@2381.46,2606.16
  Bottom Layer w15: v4(2185.17,2390.12) 2187.6,2390.12 2198.52,2401.03 2233.36,2401.03 v3(2262.52,2430.2)
NetQ10_4: Q10.4 U9.21 | length 1366.5
  Top Layer w10: U9.21@2164.63,2299.27 2261.58,2299.27 v3(2263.08,2300.77) ; v3(3395.16,2173.47) 3429.5,2173.47 3433.5,2177.47 Q10.4@3433.5,2181.84
  Bottom Layer w10: v3(2263.08,2300.77) 3333.13,2300.77 3395.16,2238.75 v3(3395.16,2173.47)
NetQ12_3: Q12.3 R46.1 | length 57.7
  Top Layer w8: Q12.3@1643.07,1782.53 R46.1@1643.07,1840.2
NetQ13_4: Q13.4 U10.31 | length 593.6
  Top Layer w12: v4(1981.9,1034.98) 1982.16,1034.72 2011.9,1034.72 2044.72,1001.89 U10.31@2044.72,982.4
  Top Layer w15: v1(1648.89,1222.89) 1651.76,1220.02 1651.76,1198.65 1657.67,1192.74 Q13.4@1678.09,1192.74
  Bottom Layer w12: v1(1648.89,1222.89) 1648.89,1167.57 1655.92,1160.54 1707.66,1160.54 1707.84,1160.72 1725.1,1160.72 1725.29,1160.54 1774.26,1160.54 1899.82,1034.98 v4(1981.9,1034.98)
NetQ16_4: Q16.4 U10.24 | length 452.3
  Top Layer w10: U10.24@2162.83,958.78 2163.58,958.03 2199.43,958.03 2222.09,980.69 2222.09,1000.89 2222,1000.98 2222,1023.89 v3(2220.09,1025.8)
  Top Layer w15: Q16.4@2382.18,1118.57 2383.76,1120.15 2383.76,1203.06 v1(2385.33,1204.63)
  Bottom Layer w12: v3(2220.09,1025.8) 2221.62,1027.34 2221.62,1045.63 2380.62,1204.63 v1(2385.33,1204.63)
NetQ17_4: Q17.4 U10.21 | length 1233.5
  Top Layer w10: U10.21@2162.83,911.53 2235.93,911.53 2239.98,907.48 v3(2265.93,907.48) ; v3(3302.41,807.31) 3304.32,805.4 3304.32,792.77 3317.3,779.8 Q17.4@3317.3,768.3
  Bottom Layer w10: v3(2265.93,907.48) 3211.76,907.48 3256.13,863.11 3256.13,853.59 v3(3302.41,807.31)
NetQ18_3: Q18.3 R90.1 | length 75.6
  Top Layer w8: R90.1@3865.58,5037.55 Q18.3@3865.58,5113.18
NetQ19_3: Q19.3 R70.1 | length 61.9
  Top Layer w10: Q19.3@1580.95,429.4 1580.95,487.14 R70.1@1583.9,490.1
NetQ20_3: Q20.3 R86.1 | length 78.5
  Top Layer w8: R86.1@3995,5037.55 Q20.3@3995,5116.06
NetQ21_3: Q21.3 R84.2 | length 293.3
  Top Layer w10: R84.2@2933.07,1907.48 2933.07,1875.49 3089.07,1719.5 Q21.3@3089.07,1678.75
NetR6_2: R6.2 R87.2 U1.4 | length 167.1
  Top Layer w10: R6.2@1701.76,3355.94 R87.2@1764.26,3355.94 1764.26,3356.92 1792.56,3385.23 U1.4@1856.16,3385.23
NetR16_1: R16.1 R89.2 R95.1 U14.3 | length 221.9
  Top Layer w8: R16.1@1318.9,4312.02 1326.77,4319.89 R95.1@1385.83,4319.89 ; R89.2@1356.3,4386.82 R89.2@1354.33,4388.79 1355.32,4388.79 1385.83,4358.28 R95.1@1385.83,4319.89 ; U14.3@1391.73,4255.92 1391.73,4313.99 R95.1@1385.83,4319.89
NetR20_1: R20.1 R21.2 R109.1 TP8.1 | length 189.9
  Top Layer w10: R21.2@2742.31,2332.27 R109.1@2807.64,2332.27 ; TP8.1@2807.64,2395.07 R109.1@2807.64,2332.27 ; R20.1@2869.38,2332.27 R109.1@2807.64,2332.27
NetR20_2: R20.2 U7.4 | length 81.1
  Top Layer w10: U7.4@2869.38,2188.18 R20.2@2869.38,2269.28
NetR37_1: R37.1 R40.2 U9.18 | length 1020.2
  Top Layer w10: R40.2@1544.8,1957.89 1551.05,1951.64 1607.2,1951.64 R37.1@1613.45,1957.88 1669.98,1957.88 1696.87,1931 1989.28,1931 2004.36,1946.08 2079.2,1946.08 2085.03,1940.26 2150.97,1940.26 v3(2151.06,1940.16) ; U9.18@2165.04,2252.02 2195.38,2252.02 2229.58,2217.82 v3(2229.58,2217.16)
  Bottom Layer w10: v3(2151.06,1940.16) 2229.58,2018.68 v3(2229.58,2217.16)
NetR61_1: R61.1 R64.2 U10.18 | length 1178.9
  Top Layer w10: R64.2@1562.79,596.97 1664.99,596.97 1735.91,526.05 1995.77,526.05 2020.98,551.26 2100.28,551.26 2139.41,512.13 v3(2262.79,512.13) ; U10.18@2163.24,864.29 2180.91,864.29 2212.09,833.11 2212.09,823.01 v3(2214,821.09)
  Bottom Layer w10: v3(2214,821.09) 2285.93,749.17 2285.93,535.26 v3(2262.79,512.13)
NetR69_2: R69.2 R83.1 U12.1 | length 143.1
  Top Layer w10: U12.1@2812.89,4382 2812.89,4451.62 R69.2@2815.84,4454.57 R83.1@2885.12,4454.57
NetR93_2: R93.2 U12.12 | length 126.3
  Top Layer w8: U12.12@2812.89,4238.3 2812.89,4229.44 2865.29,4177.04 2887.86,4177.04 R93.2@2902.56,4162.34
NetR94_2: R94.2 U12.13 | length 74.6
  Top Layer w8: U12.13@2846.35,4271.76 2848.26,4269.86 2859.01,4269.86 2901.57,4227.3 R94.2@2902.56,4227.3
NetR97_1: R97.1 R100.2 R101.1 U15.3 | length 208.8
  Top Layer w8: R101.1@1400.7,2886.21 1404.64,2890.14 U15.3@1404.64,2950.18 ; R101.1@1401.68,2886.21 1403.94,2888.46 1429.53,2888.46 1439.78,2898.72 1462.42,2898.72 R100.2@1467.63,2903.92 1467.63,2902.94 R97.1@1536.52,2902.94
NetR103_2: R103.2 U1.3 | length 77
  Top Layer w10: R103.2@1786.34,3422.29 1800.04,3408.58 1821.15,3408.58 1824.82,3404.91 U1.3@1856.16,3404.91
PROCHOT_A: R38.1 U9.11 | length 139.1
  Top Layer w10: R38.1@2058.33,2085.67 2057.34,2085.67 2046.6,2096.42 2046.6,2134.38 2045.9,2135.08 2045.9,2165.56 2062.27,2181.93 U9.11@2062.27,2212.24
PROCHOT_B: R62.1 U10.11 | length 136.6
  Top Layer w10: U10.11@2060.47,824.51 2060.47,764.55 2064.41,760.6 2064.41,690.74 R62.1@2065.26,689.89
PS_ID: D3.3 J12.1 R5.1 R85.2 U14.4 | length 1894.4
  Top Layer w8: J12.1@765.27,3029.53 775.11,3029.53 853.85,3108.27 R5.1@1013.78,3108.27 1028.48,3093.57 1028.48,3083.72 1053.15,3059.06 D3.3@1053.15,3055.12 1055.12,3053.15 1129.92,3053.15 v3(1131.89,3051.18) ; D3.3@1053.15,3060.09 1067.98,3074.91 1067.98,3093.57 R85.2@1082.68,3108.27 ; v3(1391.6,4112.61) 1391.67,4112.67 U14.4@1391.73,4167.33 U14.4@1391.73,4167.33
  Bottom Layer w8: J12.1@765.27,3029.53 775.11,3029.53 1391.6,3646.02 v3(1391.6,4112.61)
PS_ID_CMP: R95.2 TP10.1 U11.3 U14.1 | length 2128.8
  Top Layer w8: U14.1@1442.91,4255.92 1442.91,4313.99 R95.2@1448.82,4319.89 TP10.1@1505.91,4319.89 ; v3(1525.59,4280.52) 1523.29,4282.82 1523.29,4294.02 1505.91,4311.4 TP10.1@1505.91,4319.89 ; U11.3@3261.54,4286.35 3051.2,4286.35 3024.81,4259.97 3024.81,4153.13 3006.31,4134.64 2722.39,4134.64 2671.28,4185.75 2159.91,4185.75 2025.77,4319.89 TP10.1@1505.91,4319.89
PSYS_A: R44.1 U9.10 | length 144.5
  Top Layer w10: R44.1@2003.21,2085.67 2005.18,2087.64 2005.18,2153.23 2044.71,2192.76 2044.71,2193.06 2046.52,2194.87 U9.10@2046.52,2212.24
PSYS_B: R68.1 U10.10 | length 165
  Top Layer w10: R68.1@2011.13,689.89 2012.11,689.89 2041.09,718.87 2041.09,730.09 ; v3(2026.56,733.41) 2028.48,731.5 2039.67,731.5 2041.09,730.09 ; U10.10@2044.72,824.51 2044.72,733.72 2041.09,730.09
REGN_A: C76.1 R35.1 U9.28 | length 953.1
  Top Layer w8: v9(1578.94,1970.64) 1580.99,1970.64 1592.99,1982.63 1690.87,1982.63 1716.76,1956.75 R35.1@1717.74,1956.75 ; C76.1@2089.82,2443.02 2090.82,2442.03 2090.82,2421.17 2096.88,2415.1 v3(2096.88,2412.39) ; U9.28@2093.76,2370.54 2095.51,2372.29 2095.51,2412.3 v3@2095.7,2412.49
  Bottom Layer w10: v9(1578.94,1970.64) 1578.94,2007.21 1879.61,2307.88 1991.07,2307.88 2095.58,2412.39 v3(2096.88,2412.39)
REGN_B: C130.1 R59.1 U10.28 | length 777.8
  Top Layer w8: R59.1@1711.62,596.97 1723.36,608.72 1738.77,608.72 1745.02,614.97 v9(1747.73,614.97) ; C130.1@2078.88,1078.18 C130.1@2084.53,1078.18 ; C130.1@2080.35,1078.18 2091.52,1067.01 2091.52,1048.66 2095.25,1044.93 v3(2095.25,1042.22) 2094.71,1041.69 2094.71,1012.27 2091.96,1009.52 U10.28@2091.96,982.81
  Bottom Layer w10: v9(1747.73,614.97) 1747.73,787.66 1962.59,1002.52 2055.55,1002.52 v3(2095.25,1042.22)
SAFETY_A: J6.11 R22.1 R91.2 U11.5 | length 2635.2
  Top Layer w8: v3@1270.67,4970.47 1270.94,4970.75 1270.94,4992.47 J6.11@1334.11,5055.64 ; v3(3105.68,4252.31) 3108.93,4252.31 3114.26,4246.98 U11.5@3261.54,4246.98
  Top Layer w10: R91.2@1270.67,5155.51 R22.1@1334.11,5155.51 J6.11@1334.11,5055.64
  Bottom Layer w8: v3@1270.67,4970.47 1272.97,4968.18 1272.97,4958.03 1275.36,4955.64 1275.45,4955.64 1339.36,4891.73 2575.43,4891.73 3105.68,4361.48 v3(3105.68,4252.31)
  other v3: 1271.82,4969.32
SAFETY_B: J6.12 R41.1 R92.2 U11.6 | length 2502.3
  Top Layer w8: v3(3105.68,4223.56) 3108.39,4223.56 3112.13,4227.3 U11.6@3261.54,4227.3
  Top Layer w10: R41.1@1270.67,4856.3 R92.2@1334.11,4856.3 J6.12@1334.11,4955.64
  Bottom Layer w8: J6.12@1334.11,4955.64 1385.03,4904.73 2580.82,4904.73 3055.29,4430.26 3124.68,4360.87 3124.68,4242.56 v3(3105.68,4223.56)
SBW_TCK: J4.7 U11.2 | length 1985.4
  Top Layer w8: v3(3207.76,4307.45) 3208.46,4306.74 3260.84,4306.74 U11.2@3261.54,4306.04 ; v3(3837.04,4099.28) 4061.84,4099.28 4073.42,4087.69 4540.28,4087.69 4570.14,4117.55 4570.14,4371.77 4535.21,4406.69 4535.21,4446.62 J4.7@4527.66,4454.17
  Bottom Layer w8: v3(3207.76,4307.45) 3235.25,4307.45 3245.35,4297.35 3245.35,4114.15 3264.68,4094.82 3664.4,4094.82 3668.86,4099.28 v3(3837.04,4099.28)
SBW_TDIO: C141.1 J4.1 R72.1 U11.1 | length 1689.1
  Top Layer w8: v3(3207.76,4332.57) 3211,4332.57 3217.85,4325.72 U11.1@3261.54,4325.72 ; v1(4106.19,4162.34) 4222.6,4162.34 4223.58,4163.32 ; R72.1@4223.58,4191.86 4223.58,4163.32 ; J4.1@4527.66,4154.17 4486.18,4112.69 4370.29,4112.69 4355.16,4127.82 C141.1@4223.58,4127.82 4223.58,4163.32
  Bottom Layer w8: v3(3207.76,4332.57) 3234.23,4332.57 3259.35,4307.45 3259.35,4119.95 3270.48,4108.82 3658.6,4108.82 3712.11,4162.34 v1(4106.19,4162.34)
SRN_A: C65.2 C73.1 R29.1 U9.19 | length 1983.4
  Top Layer w10: U9.19@2165.04,2267.77 2198.39,2267.77 2199.14,2267.02 2202.1,2267.02 2204.92,2264.2 2222.06,2264.2 2227.06,2259.2 v3(2229.76,2259.2) ; R29.1@3715.87,1694.94 3717.41,1693.39 v3(3717.41,1653.43)
  Bottom Layer w10: v3(2229.76,2259.2) 2231.54,2257.42 3043.18,2257.42 3558.42,1742.18 C73.1@3653.86,1742.18 3653.86,1703.64 C65.2@3662.56,1694.94 ; C65.2@3664.53,1694.94 C65.2@3662.56,1694.94 ; v3(3717.41,1653.43) 3683.21,1619.23 3639.73,1619.23 3633.87,1625.08 3633.87,1666.24 C65.2@3662.56,1694.94
SRN_B: C119.2 C127.1 R53.1 U10.19 | length 1776
  Top Layer w10: U10.19@2163.24,880.04 2186.37,880.04 2200.99,865.42 2219.48,865.42 v3(2221.39,863.51) ; R53.1@3537.72,303.35 3538.7,302.36 v3(3577.09,302.36)
  Bottom Layer w10: v3(2221.39,863.51) 2888.41,863.51 3429.87,322.05 C127.1@3482.6,322.05 ; C119.2@3490.47,279.35 3490.47,314.18 C127.1@3482.6,322.05 ; v3(3577.09,302.36) 3577.09,329.3 3558.59,347.8 3509.33,347.8 3483.58,322.05 C127.1@3482.6,322.05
